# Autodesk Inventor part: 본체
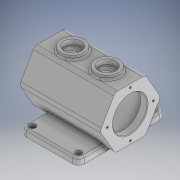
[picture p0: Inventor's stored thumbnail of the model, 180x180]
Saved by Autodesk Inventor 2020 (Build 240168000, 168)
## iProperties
Created: 2021-06
Part Number: 본체
Material: 일반
Document SubType Name: Modeling
Designer: 605-01
Density: 1 g/cm^3
Appearance: 기본값
Author: 605-01
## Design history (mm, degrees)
sketch "스케치1"
  geometry: L1 (-50, -75)-(50, -75); L2 (50, -75)-(50, 75); L3 (50, 75)-(-50, 75); L4 (-50, 75)-(-50, -75); L5 (-50, -75)-(50, 75); L6 (50, -75)-(-50, 75); 1 further point
  constraints: 12 end point, 2 midpoint, 2 parallel, 1 horizontal, 1 perpendicular
  dimensions: "d0" = 100 distance of L3.end L2.end; "d1" = 150 distance of L2.end L1.end
extrude "돌출1" new body sketch "스케치1" distance "d2" = 12; taper "d3" = 0 deg
node "작업 평면3"
sketch "스케치5" dims "d15" = 105
  geometry: L1 (75, 0)-(-75, 0) reference; L2 (-75, 0)-(-75, 12) reference; L3 (75, 12)-(-75, 12) reference; L4 (75, 0)-(75, 12) reference; L5 (-52.5, 50)-(-26.25, 95.466); L6 (-26.25, 95.466)-(26.25, 95.466); L7 (26.25, 95.466)-(52.5, 50); L8 (52.5, 50)-(26.25, 4.534); L9 (26.25, 4.534)-(-26.25, 4.534); L10 (-26.25, 4.534)-(-52.5, 50); 4 further points
  constraints: 12 end point, 1 coincident, 1 horizontal alignment, 1 midpoint, 1 vertical alignment, 15 other
  dimensions: "d16" = 50 distance from line of L1 point (0, 50); "d17" = 50 distance from line of L1 L7.end
extrude "돌출2" join sketch "스케치5" distance "d18" = 140; taper "d19" = 0 deg
sketch "스케치6"
  geometry: L1 (75, 50)-(75, 95.466) reference; L2 (75, 95.466)-(-65, 95.466) reference; L3 (-65, 50)-(-65, 95.466) reference; L4 (75, 50)-(-65, 50) reference; L5 (-50, 12)-(-50, 4.534) reference; L6 (50, 12)-(-50, 12) reference; L7 (50, 4.534)-(50, 12) reference; L8 (75, 4.534)-(50, 4.534) reference; L9 (75, 4.534)-(75, 50) reference; L10 (75, 50)-(-65, 50) reference; L11 (-65, 4.534)-(-65, 50) reference; L12 (-50, 4.534)-(-65, 4.534) reference; L13 (75, 80)-(63, 80); L14 (63, 80)-(63, 82.5); L15 (58, 87.5)-(-48, 87.5); L16 (-53, 82.5)-(-53, 80); L17 (-53, 80)-(-65, 80); L18 (75, 80)-(75, 50); L19 (75, 50)-(-65, 50); L20 (-65, 50)-(-65, 80); L21 (-50, 0)-(50, 0) reference; A1 r 5 centre (58, 82.5) between (63, 82.5) and (58, 87.5); A2 r 5 centre (-48, 82.5) between (-48, 87.5) and (-53, 82.5); 1 further point
  constraints: 16 end point, 6 point on line, 4 point on circle, 4 tangent, 3 perpendicular, 2 centre point, 2 horizontal, 1 collinear, 1 equal radius
  dimensions: "d20" = 12 distance of L13.start L13.end; "d21" = 12 distance of L16.end L17.end; "d22" = 50 distance from line of L19.end L21; "d23" = 5 radius of A1; "d24" = 75 diameter of L15 L10; "d25" = 60 diameter of L13 L4
revolve "회전1" sketch "스케치6" stored, may be unused: angle "d26" = 90 deg
node "작업 평면4"
sketch "스케치8"
  geometry: L1 (-75, 26.25)-(-75, -26.25) reference; C1 r 20 at (-35, 0); C2 r 20 at (25, 0); 1 further point
  constraints: 2 centre point, 2 horizontal alignment
  dimensions: "d36" = 40 diameter of C1; "d37" = 40 diameter of C2; "d38" = 40 distance from line of C1.centre L1; "d39" = 60 distance of C2.centre C1.centre
extrude "돌출3" join sketch "스케치8" stored distance "d40" = 140; taper "d41" = 0 deg
sketch "스케치9"
  geometry: C1 r 20 at (0, 0) reference; C2 r 20 at (60, 0) reference; 4 further points
  constraints: 3 coincident
hole "구멍1" sketch "스케치9" at (0, 0), (60, 0) diameter "d42" = 25; stored, may be unused: countersink angle "d46" = 90 deg, drill point angle "d48" = 0 deg; dims "d43" = 6, "d44" = 30, "d45" = 8, "d47" = 8
chamfer "모따기1" distance "d49" = 1; stored, may be unused: second distance "d50" = 2, angle "d51" = 45 deg
sketch "스케치10"
  geometry: L1 (50, 0)-(78.284, 28.284); L2 (50, 0)-(90, 0); C1 r 30 at (50, 0) reference; A1 r 40 centre (50, 0) between (78.284, 28.284) and (90, 0); 2 further points
  constraints: 4 end point, 2 coincident, 2 point on circle, 1 centre point, 1 horizontal
  dimensions: "d52" = 80 diameter of A1; "d53" = 45 deg angle of L2 L1
hole "구멍2" sketch "스케치10" at (78.284, 28.284) diameter "d54" = 3.45873; stored, may be unused: countersink angle "d58" = 90 deg, drill point angle "d60" = 118 deg; dims "d55" = 8, "d56" = 30, "d57" = 8, "d59" = 10
sketch "스케치11" dims "d64" = 80
  geometry: L1 (-50, 0)-(-90, 0); C1 r 31 at (-50, 0) reference; 2 further points
  constraints: 2 coincident, 2 end point, 1 horizontal, 1 horizontal alignment, 2 other
hole "구멍3" sketch "스케치11" at (-90, 0) diameter "d65" = 3.45873; stored, may be unused: countersink angle "d69" = 90 deg, drill point angle "d71" = 118 deg; dims "d66" = 8, "d67" = 30, "d68" = 8, "d70" = 10
fillet "모깎기1" dims "d75" = 8
fillet "모깎기2" dims "d76" = 10
sketch "스케치12"
  geometry: A1 r 10 centre (-40, -65) between (-50, -65) and (-40, -75) reference; A2 r 10 centre (40, -65) between (40, -75) and (50, -65) reference; A3 r 10 centre (40, 65) between (50, 65) and (40, 75) reference; A4 r 10 centre (-40, 65) between (-40, 75) and (-50, 65) reference; 5 further points
  constraints: 4 coincident
hole "구멍4" sketch "스케치12" at (-40, -65), (40, -65), (40, 65), (-40, 65) diameter "d77" = 11; stored, may be unused: countersink angle "d81" = 90 deg, drill point angle "d83" = 118 deg; dims "d78" = 8, "d79" = 30, "d80" = 8, "d82" = 10
fillet "모깎기3" dims "d84" = 3
sketch "스케치13"
  geometry: L1 (20.739, 57.998)-(-20.739, 57.998); L2 (-20.739, 57.998)-(-20.739, 64.002); L3 (-20.739, 64.002)-(20.739, 64.002); L4 (20.739, 64.002)-(20.739, 57.998); L5 (20.739, 57.998)-(-20.739, 64.002); L6 (-50, 65)-(-50, 32.293) reference; L7 (40, 75)-(-40, 75) reference; 2 further points
  constraints: 2 end point, 1 midpoint, 2 other
  dimensions: "d85" = 50 distance from line of point (0, 61) L6; "d86" = 14 distance from line of point (0, 61) L7
feature "엠보싱1" sketch "스케치13" dims "d87" = 0.5, "d88" = 0
node "솔리드1"
pattern_circular "원형 패턴1" dims angle "d62" = 360 deg
pattern_circular "원형 패턴2" dims angle "d73" = 360 deg
node "투영된 루프1"
node "투영된 루프2"
node "투영된 루프3"
feature "A9D066F2-1C7D-4E18-AEED-F7BC21143FA4" dims "d77" = 11, "d78" = 8, "d79" = 30, "d80" = 8, "d81" = 90 deg, "d82" = 10, "d83" = 118 deg
other parameters: "d14" = -75, "d31" = 102.5
